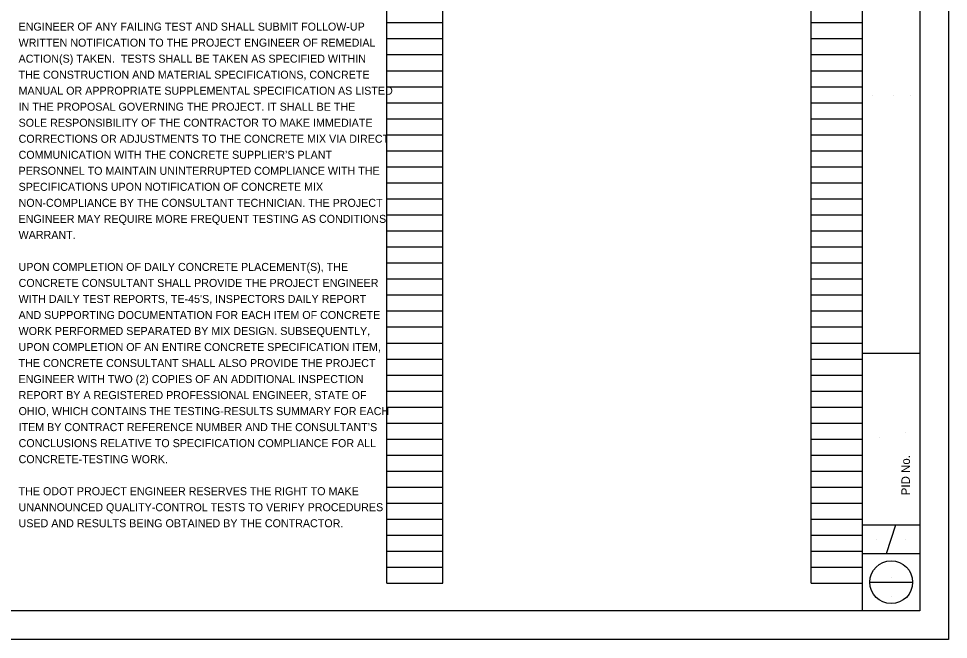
# Model space of a CAD drawing. Extents: x -14.8 to 34, y 0 to 43.2.
# Drawn here: x 17.74 to 34, y 0 to 10.85 of the extents above; entities that cross this region are included whole.
import ezdxf

# ---------------------------------------------------------------- set-up
doc = ezdxf.new("R2010")
doc.units = 0
for name, color, linetype in [('SH_Border', 7, 'Continuous'), ('SH_Cut_Line', 7, 'Continuous'), ('SH_Data', 7, 'Continuous'), ('SH_Text', 7, 'Continuous')]:
    doc.layers.add(name, color=color, linetype=linetype)

msp = doc.modelspace()

# ---------------------------------------------------------------- linework, layer by layer
at = {"layer": 'SH_Border'}
for p, q in [((32.5, 0.5), (32.5, 21.5)), ((32.5, 5), (33.5, 5)), ((32.5, 2), (33.5, 2)), ((32.917, 1.5), (33.083, 2)), ((32.5, 1.5), (33.5, 1.5))]:
    msp.add_line(p, q, dxfattribs=at)
msp.add_lwpolyline([(2, 21.5), (33.5, 21.5), (33.5, 0.5), (2, 0.5)], close=True, dxfattribs=at)
at = {"layer": 'SH_Cut_Line'}
msp.add_lwpolyline([(0, 22), (34, 22), (34, 0), (0, 0)], close=True, dxfattribs=at)
at = {"layer": 'SH_Data'}
for p, q in [((24.18, 0.98), (24.18, 21.14)), ((25.16, 0.98), (25.16, 21.14)), ((31.6, 0.98), (31.6, 21.14)), ((32.5, 0.98), (32.5, 21.14)), ((24.18, 10.78), (25.16, 10.78)), ((31.6, 10.78), (32.5, 10.78)), ((24.18, 10.5), (25.16, 10.5)), ((31.6, 10.5), (32.5, 10.5)), ((24.18, 10.22), (25.16, 10.22)), ((31.6, 10.22), (32.5, 10.22)), ((24.18, 9.94), (25.16, 9.94)), ((31.6, 9.94), (32.5, 9.94)), ((24.18, 9.66), (25.16, 9.66)), ((31.6, 9.66), (32.5, 9.66)), ((32.667, 9.5), (32.667, 9.5)), ((33.042, 9.5), (33.042, 9.5)), ((33.333, 9.5), (33.333, 9.5)), ((24.18, 9.38), (25.16, 9.38)), ((31.6, 9.38), (32.5, 9.38)), ((24.18, 9.1), (25.16, 9.1)), ((31.6, 9.1), (32.5, 9.1)), ((24.18, 8.82), (25.16, 8.82)), ((31.6, 8.82), (32.5, 8.82)), ((24.18, 8.54), (25.16, 8.54)), ((31.6, 8.54), (32.5, 8.54)), ((24.18, 8.26), (25.16, 8.26)), ((31.6, 8.26), (32.5, 8.26)), ((24.18, 7.98), (25.16, 7.98)), ((31.6, 7.98), (32.5, 7.98)), ((24.18, 7.7), (25.16, 7.7)), ((31.6, 7.7), (32.5, 7.7)), ((24.18, 7.42), (25.16, 7.42)), ((31.6, 7.42), (32.5, 7.42)), ((24.18, 7.14), (25.16, 7.14)), ((31.6, 7.14), (32.5, 7.14)), ((24.18, 6.86), (25.16, 6.86)), ((31.6, 6.86), (32.5, 6.86)), ((24.18, 6.58), (25.16, 6.58)), ((31.6, 6.58), (32.5, 6.58)), ((24.18, 6.3), (25.16, 6.3)), ((31.6, 6.3), (32.5, 6.3)), ((24.18, 6.02), (25.16, 6.02)), ((31.6, 6.02), (32.5, 6.02)), ((24.18, 5.74), (25.16, 5.74)), ((31.6, 5.74), (32.5, 5.74)), ((24.18, 5.46), (25.16, 5.46)), ((31.6, 5.46), (32.5, 5.46)), ((24.18, 5.18), (25.16, 5.18)), ((31.6, 5.18), (32.5, 5.18)), ((24.18, 4.9), (25.16, 4.9)), ((31.6, 4.9), (32.5, 4.9)), ((24.18, 4.62), (25.16, 4.62)), ((31.6, 4.62), (32.5, 4.62)), ((24.18, 4.34), (25.16, 4.34)), ((31.6, 4.34), (32.5, 4.34)), ((24.18, 4.06), (25.16, 4.06)), ((31.6, 4.06), (32.5, 4.06)), ((24.18, 3.78), (25.16, 3.78)), ((31.6, 3.78), (32.5, 3.78)), ((33.25, 3.618), (33.25, 3.618)), ((24.18, 3.5), (25.16, 3.5)), ((31.6, 3.5), (32.5, 3.5)), ((32.8, 3.53), (32.8, 3.53)), ((24.18, 3.22), (25.16, 3.22)), ((31.6, 3.22), (32.5, 3.22)), ((24.18, 2.94), (25.16, 2.94)), ((31.6, 2.94), (32.5, 2.94)), ((24.18, 2.66), (25.16, 2.66)), ((31.6, 2.66), (32.5, 2.66)), ((24.18, 2.38), (25.16, 2.38)), ((31.6, 2.38), (32.5, 2.38)), ((24.18, 2.1), (25.16, 2.1)), ((31.6, 2.1), (32.5, 2.1)), ((24.18, 1.82), (25.16, 1.82)), ((31.6, 1.82), (32.5, 1.82)), ((32.75, 1.75), (32.75, 1.75)), ((33.25, 1.75), (33.25, 1.75)), ((24.18, 1.54), (25.16, 1.54)), ((31.6, 1.54), (32.5, 1.54)), ((24.18, 1.26), (25.16, 1.26)), ((31.6, 1.26), (32.5, 1.26)), ((24.18, 0.98), (25.16, 0.98)), ((31.6, 0.98), (32.5, 0.98)), ((32.625, 1), (33.375, 1)), ((33, 1.085), (33, 1.085)), ((33, 0.745), (33, 0.745))]:
    msp.add_line(p, q, dxfattribs=at)
msp.add_circle((33, 1), 0.375, dxfattribs=at)

# ---------------------------------------------------------------- texts
msp.add_text('PID No.', height=0.15, rotation=90, dxfattribs=at).set_placement((33.327, 2.519))
at = {"layer": 'SH_Text'}
for s, p in [('ENGINEER OF ANY FAILING TEST AND SHALL SUBMIT FOLLOW-UP ', (17.74, 10.64)), ('WRITTEN NOTIFICATION TO THE PROJECT ENGINEER OF REMEDIAL ', (17.74, 10.36)), ('ACTION(S) TAKEN.  TESTS SHALL BE TAKEN AS SPECIFIED WITHIN ', (17.74, 10.08)), ('THE CONSTRUCTION AND MATERIAL SPECIFICATIONS, CONCRETE ', (17.74, 9.8)), ('MANUAL OR APPROPRIATE SUPPLEMENTAL SPECIFICATION AS LISTED ', (17.74, 9.52)), ('IN THE PROPOSAL GOVERNING THE PROJECT. IT SHALL BE THE ', (17.74, 9.24)), ('SOLE RESPONSIBILITY OF THE CONTRACTOR TO MAKE IMMEDIATE ', (17.74, 8.96)), ('CORRECTIONS OR ADJUSTMENTS TO THE CONCRETE MIX VIA DIRECT ', (17.74, 8.68)), ('COMMUNICATION WITH THE CONCRETE SUPPLIER’S PLANT ', (17.74, 8.4)), ('PERSONNEL TO MAINTAIN UNINTERRUPTED COMPLIANCE WITH THE ', (17.74, 8.12)), ('SPECIFICATIONS UPON NOTIFICATION OF CONCRETE MIX ', (17.74, 7.84)), ('NON-COMPLIANCE BY THE CONSULTANT TECHNICIAN. THE PROJECT ', (17.74, 7.56)), ('ENGINEER MAY REQUIRE MORE FREQUENT TESTING AS CONDITIONS ', (17.74, 7.28)), ('WARRANT.', (17.74, 7)), ('UPON COMPLETION OF DAILY CONCRETE PLACEMENT(S), THE ', (17.74, 6.44)), ('CONCRETE CONSULTANT SHALL PROVIDE THE PROJECT ENGINEER ', (17.74, 6.16)), ("WITH DAILY TEST REPORTS, TE-45'S, INSPECTORS DAILY REPORT ", (17.74, 5.88)), ('AND SUPPORTING DOCUMENTATION FOR EACH ITEM OF CONCRETE ', (17.74, 5.6)), ('WORK PERFORMED SEPARATED BY MIX DESIGN. SUBSEQUENTLY, ', (17.74, 5.32)), ('UPON COMPLETION OF AN ENTIRE CONCRETE SPECIFICATION ITEM, ', (17.74, 5.04)), ('THE CONCRETE CONSULTANT SHALL ALSO PROVIDE THE PROJECT ', (17.74, 4.76)), ('ENGINEER WITH TWO (2) COPIES OF AN ADDITIONAL INSPECTION ', (17.74, 4.48)), ('REPORT BY A REGISTERED PROFESSIONAL ENGINEER, STATE OF ', (17.74, 4.2)), ('OHIO, WHICH CONTAINS THE TESTING-RESULTS SUMMARY FOR EACH ', (17.74, 3.92)), ('ITEM BY CONTRACT REFERENCE NUMBER AND THE CONSULTANT’S ', (17.74, 3.64)), ('CONCLUSIONS RELATIVE TO SPECIFICATION COMPLIANCE FOR ALL ', (17.74, 3.36)), ('CONCRETE-TESTING WORK.', (17.74, 3.08)), ('THE ODOT PROJECT ENGINEER RESERVES THE RIGHT TO MAKE ', (17.74, 2.52)), ('UNANNOUNCED QUALITY-CONTROL TESTS TO VERIFY PROCEDURES ', (17.74, 2.24)), ('USED AND RESULTS BEING OBTAINED BY THE CONTRACTOR.', (17.74, 1.96))]:
    msp.add_text(s, height=0.14, dxfattribs=at).set_placement(p)

doc.saveas('drawing.dxf')
